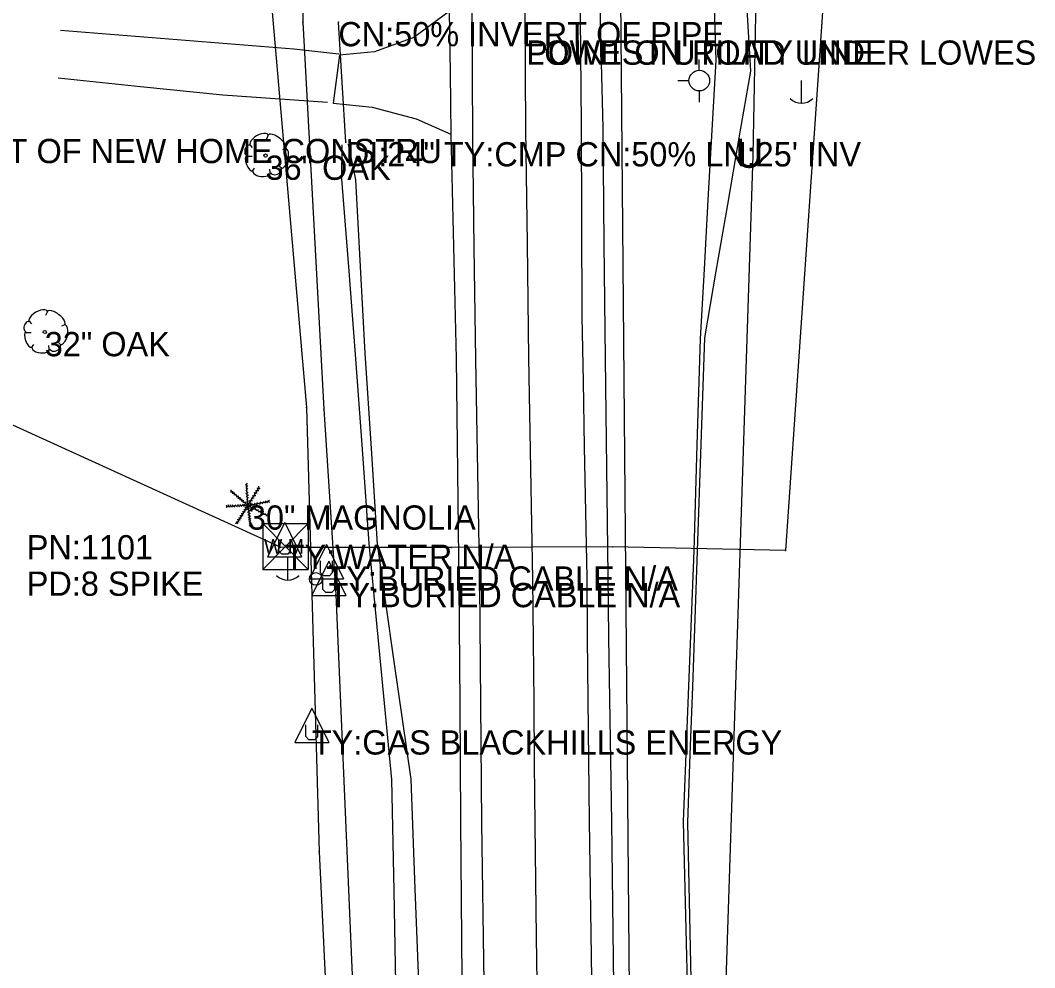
# Model space of a CAD drawing. Extents: x 1804576 to 1805329, y 515859 to 519427.
# Drawn here: x 1804848.7 to 1805057.8, y 517390.7 to 517586 of the extents above; entities that cross this region are included whole.
import ezdxf

# ---------------------------------------------------------------- set-up
doc = ezdxf.new("R2010")
doc.units = 0
for name, color, linetype in [('Default', 7, 'Continuous'), ('S_BASELINE', 7, 'Continuous'), ('S_DITCHLINE', 7, 'Continuous'), ('S_DRG_PT_SYM', 7, 'Continuous'), ('S_DRIVEWAY', 7, 'Continuous'), ('S_EDGE_PAVEMENT', 7, 'Continuous'), ('S_ELECTRIC_UTILITIES_ANNOT', 7, 'Continuous'), ('S_FIBER_OPTIC_CABLE', 7, 'Continuous'), ('S_GAS_UTILITIES', 7, 'Continuous'), ('S_MSC_PT_SYM', 7, 'Continuous'), ('S_PAVEMENT_CROWN', 7, 'Continuous'), ('S_SECONDARY_CTL_ANNOT', 7, 'Continuous'), ('S_SHOULDER', 7, 'Continuous'), ('S_SIDE_DRAIN', 7, 'Continuous'), ('S_SIDE_DRAIN_ANNOT', 7, 'Continuous'), ('S_SURVEY_TEXT_ANNOT', 7, 'Continuous'), ('S_TREE', 7, 'Continuous'), ('S_TREE_ANNOT', 7, 'Continuous'), ('S_UNDERGROUND_CABLE', 7, 'Continuous'), ('S_UTILITY_POLE', 7, 'Continuous'), ('S_UTILITY_POLE_ANNOT', 7, 'Continuous'), ('S_UTL_PT_SYM', 7, 'Continuous'), ('S_WATER_UTILITIES', 7, 'Continuous')]:
    doc.layers.add(name, color=color, linetype=linetype)

msp = doc.modelspace()

# ---------------------------------------------------------------- linework, layer by layer
at = {"layer": 'S_BASELINE'}
msp.add_line((1804979.02, 516850.02), (1804971.48, 517701.71), dxfattribs=at)
at = {"layer": 'S_DITCHLINE'}
for points in [[(1804992.34, 517629.48), (1804990.73, 517622.13), (1804991.4, 517599.91), (1804992.07, 517577.69), (1804991.26, 517563.34), (1804990.45, 517548.98), (1804989.64, 517534.63), (1804988.82, 517520.28), (1804988.18, 517498.42), (1804987.54, 517476.57), (1804986.98, 517462.63), (1804986.42, 517448.7), (1804985.86, 517434.77), (1804985.31, 517420.83), (1804985.82, 517401.34), (1804986.33, 517381.85)], [(1804994.29, 517629.66), (1804996.5, 517622.01), (1804997.84, 517598.75), (1804999.19, 517575.49), (1804996.83, 517561.75), (1804994.47, 517548), (1804992.11, 517534.26), (1804989.75, 517520.52), (1804988.99, 517498.56), (1804988.23, 517476.6), (1804987.73, 517462.59), (1804987.24, 517448.59), (1804986.75, 517434.59), (1804986.25, 517420.59), (1804986.64, 517401.2), (1804987.03, 517381.82)], [(1804915, 517560.29), (1804914.88, 517553.22), (1804916.32, 517535.14), (1804917.76, 517517.05), (1804919.16, 517497.58), (1804920.55, 517478.12), (1804922.88, 517453.78), (1804925.2, 517429.44), (1804925.67, 517406.52), (1804926.14, 517383.6)], [(1804916.31, 517560.43), (1804917.77, 517553.06), (1804918.75, 517535.19), (1804919.74, 517517.32), (1804921, 517497.66), (1804922.27, 517478), (1804925.73, 517453.75), (1804929.18, 517429.5), (1804930.04, 517406.92), (1804930.89, 517384.33)]]:
    msp.add_lwpolyline(points, dxfattribs=at)
at = {"layer": 'S_DRG_PT_SYM'}
for points in [[(1804914.26, 517585.61), (1804914.26, 517585.66), (1804914.26, 517585.61), (1804914.21, 517585.61), (1804914.26, 517585.61), (1804914.26, 517585.56), (1804914.26, 517585.61), (1804914.31, 517585.61)], [(1804915.81, 517560.85), (1804915.81, 517560.9), (1804915.81, 517560.85), (1804915.76, 517560.85), (1804915.81, 517560.85), (1804915.81, 517560.8), (1804915.81, 517560.85), (1804915.86, 517560.85)]]:
    msp.add_lwpolyline(points, dxfattribs=at)
at = {"layer": 'S_DRIVEWAY'}
for points in [[(1804914.38, 517579.01), (1804905.05, 517580.03), (1804881.02, 517581.96), (1804857, 517583.89)], [(1804856.53, 517574.08), (1804873.5, 517572.33), (1804890.47, 517570.59), (1804912, 517569.06)]]:
    msp.add_lwpolyline(points, dxfattribs=at)
at = {"layer": 'S_EDGE_PAVEMENT'}
for points in [[(1804940.46, 517709.42), (1804940.53, 517696.33), (1804940.61, 517683.24), (1804940.74, 517670.08), (1804940.88, 517656.93), (1804941.15, 517639.79), (1804941.42, 517622.66), (1804941.59, 517605.09), (1804941.76, 517587.51), (1804941.82, 517574.8), (1804941.89, 517562.09), (1804942.21, 517539.1), (1804942.54, 517516.11), (1804942.97, 517492.9), (1804943.39, 517469.69), (1804943.57, 517445.12), (1804943.76, 517420.54), (1804944.11, 517396.98), (1804944.47, 517373.41)], [(1804962.48, 517709.57), (1804962.67, 517696.25), (1804962.86, 517682.93), (1804963.02, 517670.14), (1804963.19, 517657.36), (1804963.3, 517639.71), (1804963.4, 517622.06), (1804963.76, 517604.29), (1804964.12, 517586.52), (1804964.31, 517564.57), (1804964.38, 517544.75), (1804964.45, 517524.93), (1804964.7, 517511.48), (1804964.95, 517498.03), (1804965.2, 517484.58), (1804965.45, 517471.12), (1804965.58, 517458.56), (1804965.7, 517445.99), (1804965.83, 517433.42), (1804965.96, 517420.85), (1804966.31, 517397.71), (1804966.66, 517374.58)], [(1804937.12, 517587.77), (1804929.82, 517582.39), (1804921.73, 517579.49), (1804914.51, 517578.77), (1804913.22, 517568.91), (1804921.24, 517568.04), (1804930.31, 517565.67), (1804937.46, 517562.48)]]:
    msp.add_lwpolyline(points, dxfattribs=at)
at = {"layer": 'S_FIBER_OPTIC_CABLE'}
for p, q in [((1805001.76, 517665.3), (1804999.7, 517558.11)), ((1804907.42, 517621.23), (1804906.91, 517585.58)), ((1804906.91, 517585.58), (1804911.25, 517505.78)), ((1804999.7, 517558.11), (1804991.59, 517309.83)), ((1804911.25, 517505.78), (1804913.71, 517467.58)), ((1804913.71, 517467.58), (1804920.05, 517320.35))]:
    msp.add_line(p, q, dxfattribs=at)
at = {"layer": 'S_GAS_UTILITIES'}
for p, q in [((1804900.59, 517587.64), (1804907.72, 517506.16)), ((1804907.72, 517506.16), (1804910.28, 517414.54)), ((1804910.28, 517414.54), (1804914.92, 517321.69))]:
    msp.add_line(p, q, dxfattribs=at)
at = {"layer": 'S_MSC_PT_SYM'}
msp.add_lwpolyline([(1804952.99, 517581.81), (1804952.99, 517581.86), (1804952.99, 517581.81), (1804952.94, 517581.81), (1804952.99, 517581.81), (1804952.99, 517581.76), (1804952.99, 517581.81), (1804953.04, 517581.81)], dxfattribs=at)
at = {"layer": 'S_PAVEMENT_CROWN'}
msp.add_lwpolyline([(1804951.35, 517708.92), (1804951.32, 517696), (1804951.29, 517683.08), (1804951.43, 517670), (1804951.58, 517656.91), (1804951.88, 517639.56), (1804952.18, 517622.21), (1804952.44, 517604.51), (1804952.7, 517586.81), (1804952.87, 517563.54), (1804953.18, 517539.97), (1804953.49, 517516.4), (1804953.89, 517493.53), (1804954.28, 517470.66), (1804954.4, 517458.04), (1804954.53, 517445.43), (1804954.65, 517432.82), (1804954.78, 517420.21), (1804955.07, 517396.93), (1804955.36, 517373.65)], dxfattribs=at)
at = {"layer": 'S_SHOULDER'}
for points in [[(1804939.34, 517709.36), (1804938.44, 517696.01), (1804937.54, 517682.66), (1804937.19, 517670.12), (1804936.83, 517657.58), (1804937.23, 517639.85), (1804937.63, 517622.12), (1804937.37, 517604.95), (1804937.12, 517587.79), (1804937.29, 517575.12), (1804937.45, 517562.46), (1804938.01, 517539.37), (1804938.57, 517516.27), (1804938.84, 517492.83), (1804939.1, 517469.39), (1804939.28, 517445.13), (1804939.46, 517420.88), (1804939.67, 517396.64), (1804939.87, 517372.4)], [(1804963.34, 517709.11), (1804964.59, 517695.88), (1804965.85, 517682.65), (1804966.81, 517670), (1804967.78, 517657.34), (1804967.87, 517639.95), (1804967.96, 517622.56), (1804968.08, 517603.88), (1804968.2, 517585.21), (1804968.75, 517563.81), (1804969, 517539.98), (1804969.26, 517516.16), (1804969.52, 517493.79), (1804969.79, 517471.42), (1804969.98, 517458.76), (1804970.17, 517446.09), (1804970.36, 517433.42), (1804970.55, 517420.76), (1804970.85, 517398.22), (1804971.15, 517375.69)]]:
    msp.add_lwpolyline(points, dxfattribs=at)
at = {"layer": 'S_SIDE_DRAIN'}
msp.add_line((1804915.81, 517560.85), (1804914.26, 517585.61), dxfattribs=at)
at = {"layer": 'S_TREE'}
for p, q in [((1804899.81, 517562.33), (1804899.42, 517561.47)), ((1804896.01, 517560.31), (1804896.52, 517559.73)), ((1804895.36, 517557.99), (1804896.48, 517557.99)), ((1804903.38, 517559.54), (1804902.72, 517559.26)), ((1804896.52, 517554.81), (1804896.98, 517555.51)), ((1804902.6, 517555.43), (1804902.14, 517555.85)), ((1804900.2, 517554.54), (1804900.12, 517555.31)), ((1804854.29, 517525.96), (1804853.9, 517525.1)), ((1804850.49, 517523.94), (1804850.99, 517523.36)), ((1804857.85, 517523.17), (1804857.19, 517522.9)), ((1804849.83, 517521.62), (1804850.96, 517521.62)), ((1804850.99, 517518.44), (1804851.46, 517519.14)), ((1804854.68, 517518.17), (1804854.6, 517518.94)), ((1804857.08, 517519.06), (1804856.61, 517519.49)), ((1804892.33, 517488.71), (1804892.03, 517488.66)), ((1804895.61, 517485.96), (1804892.15, 517488.87)), ((1804892.19, 517488.85), (1804892.19, 517489.15)), ((1804892.5, 517488.6), (1804892.5, 517488.9)), ((1804892.86, 517488.31), (1804892.86, 517488.61)), ((1804895.36, 517490.04), (1804895.13, 517490.24)), ((1804895.39, 517489.48), (1804895.17, 517489.68)), ((1804895.42, 517488.91), (1804895.19, 517489.1)), ((1804895.61, 517485.96), (1804895.34, 517490.4)), ((1804895.35, 517490.29), (1804895.54, 517490.52)), ((1804895.38, 517489.81), (1804895.57, 517490.05)), ((1804895.42, 517489.21), (1804895.6, 517489.45)), ((1804895.45, 517488.5), (1804895.64, 517488.74)), ((1804895.61, 517485.96), (1804897.95, 517489.65)), ((1804897.09, 517488.31), (1804897, 517488.59)), ((1804897.25, 517488.52), (1804897.55, 517488.56)), ((1804897.39, 517488.82), (1804897.3, 517489.11)), ((1804897.57, 517489.01), (1804897.87, 517489.05)), ((1804897.68, 517489.27), (1804897.59, 517489.56)), ((1804897.82, 517489.43), (1804898.12, 517489.48)), ((1804897.93, 517489.61), (1804897.84, 517489.9)), ((1804892.68, 517488.43), (1804892.38, 517488.4)), ((1804893.04, 517488.11), (1804892.74, 517488.08)), ((1804893.5, 517487.73), (1804893.2, 517487.71)), ((1804893.27, 517487.94), (1804893.27, 517488.24)), ((1804893.86, 517487.4), (1804893.56, 517487.38)), ((1804893.68, 517487.61), (1804893.68, 517487.91)), ((1804894.19, 517487.14), (1804893.89, 517487.11)), ((1804894.01, 517487.33), (1804894.01, 517487.63)), ((1804894.53, 517486.84), (1804894.24, 517486.82)), ((1804894.37, 517487.03), (1804894.37, 517487.33)), ((1804894.9, 517486.54), (1804894.6, 517486.52)), ((1804894.74, 517486.72), (1804894.74, 517487.02)), ((1804895.1, 517486.41), (1804895.1, 517486.71)), ((1804895.44, 517488.25), (1804895.22, 517488.45)), ((1804895.48, 517487.65), (1804895.26, 517487.85)), ((1804895.52, 517487.09), (1804895.3, 517487.28)), ((1804895.53, 517486.47), (1804895.31, 517486.67)), ((1804895.52, 517487.94), (1804895.71, 517488.17)), ((1804895.53, 517487.37), (1804895.72, 517487.6)), ((1804895.56, 517486.7), (1804895.75, 517486.93)), ((1804895.61, 517485.96), (1804900.03, 517486.83)), ((1804895.96, 517486.45), (1804896.26, 517486.5)), ((1804896.06, 517486.72), (1804895.97, 517487)), ((1804896.24, 517486.92), (1804896.54, 517486.96)), ((1804896.42, 517487.25), (1804896.33, 517487.53)), ((1804896.58, 517487.46), (1804896.88, 517487.5)), ((1804896.72, 517487.74), (1804896.63, 517488.02)), ((1804896.92, 517486.21), (1804897.12, 517486.43)), ((1804896.93, 517487.98), (1804897.23, 517488.02)), ((1804897.49, 517486.34), (1804897.69, 517486.56)), ((1804897.87, 517486.4), (1804898.12, 517486.24)), ((1804898.12, 517486.48), (1804898.32, 517486.7)), ((1804898.45, 517486.51), (1804898.7, 517486.34)), ((1804898.71, 517486.57), (1804898.91, 517486.79)), ((1804898.96, 517486.62), (1804899.21, 517486.46)), ((1804899.2, 517486.67), (1804899.4, 517486.9)), ((1804899.39, 517486.71), (1804899.64, 517486.55)), ((1804899.64, 517486.76), (1804899.84, 517486.99)), ((1804899.79, 517486.77), (1804900.05, 517486.61)), ((1804899.87, 517486.82), (1804900.07, 517487.04)), ((1804891.24, 517485.75), (1804891.11, 517485.48)), ((1804895.61, 517485.96), (1804891.16, 517485.75)), ((1804891.39, 517485.77), (1804891.22, 517486.02)), ((1804891.59, 517485.78), (1804891.46, 517485.51)), ((1804891.78, 517485.8), (1804891.61, 517486.05)), ((1804891.93, 517485.8), (1804891.8, 517485.53)), ((1804892.18, 517485.8), (1804892.01, 517486.05)), ((1804892.35, 517485.81), (1804892.22, 517485.54)), ((1804892.58, 517485.83), (1804892.41, 517486.07)), ((1804892.86, 517485.83), (1804892.73, 517485.57)), ((1804893.15, 517485.84), (1804892.98, 517486.09)), ((1804895.61, 517485.96), (1804893.23, 517482.19)), ((1804893.43, 517485.86), (1804893.29, 517485.59)), ((1804893.7, 517485.88), (1804893.53, 517486.13)), ((1804893.91, 517485.88), (1804893.77, 517485.61)), ((1804894.18, 517485.89), (1804894.01, 517486.14)), ((1804894.38, 517485.91), (1804894.25, 517485.64)), ((1804894.62, 517485.93), (1804894.45, 517486.18)), ((1804894.77, 517484.65), (1804894.47, 517484.62)), ((1804894.66, 517484.45), (1804894.73, 517484.16)), ((1804894.84, 517485.91), (1804894.7, 517485.64)), ((1804895.04, 517485.1), (1804894.75, 517485.06)), ((1804894.95, 517485.97), (1804894.79, 517486.22)), ((1804894.92, 517484.87), (1804894.99, 517484.58)), ((1804895.26, 517486.25), (1804894.96, 517486.22)), ((1804895.28, 517485.47), (1804894.99, 517485.43)), ((1804895.23, 517485.92), (1804895.09, 517485.66)), ((1804895.19, 517485.31), (1804895.27, 517485.01)), ((1804895.41, 517485.64), (1804895.48, 517485.35)), ((1804895.67, 517485.29), (1804895.48, 517485.06)), ((1804895.74, 517484.71), (1804895.54, 517484.48)), ((1804895.61, 517485.96), (1804899.53, 517483.92)), ((1804895.61, 517485.96), (1804896.14, 517481.59)), ((1804895.69, 517485.54), (1804895.95, 517485.38)), ((1804895.73, 517484.98), (1804895.98, 517484.83)), ((1804895.81, 517484.41), (1804896.07, 517484.26)), ((1804895.94, 517485.78), (1804896.21, 517485.92)), ((1804895.99, 517486.05), (1804896.19, 517486.27)), ((1804896.12, 517485.69), (1804896.19, 517485.39)), ((1804896.23, 517486.08), (1804896.49, 517485.92)), ((1804896.39, 517486.11), (1804896.59, 517486.33)), ((1804896.42, 517485.56), (1804896.68, 517485.7)), ((1804896.7, 517485.38), (1804896.77, 517485.09)), ((1804896.75, 517486.16), (1804897, 517486)), ((1804896.97, 517485.25), (1804897.24, 517485.39)), ((1804897.24, 517485.11), (1804897.31, 517484.81)), ((1804897.26, 517486.27), (1804897.52, 517486.11)), ((1804897.53, 517484.97), (1804897.79, 517485.11)), ((1804897.76, 517484.83), (1804897.83, 517484.54)), ((1804898.01, 517484.71), (1804898.28, 517484.85)), ((1804898.3, 517484.54), (1804898.37, 517484.25)), ((1804898.55, 517484.44), (1804898.81, 517484.58)), ((1804899.1, 517484.16), (1804899.36, 517484.3)), ((1804893.26, 517482.27), (1804892.97, 517482.24)), ((1804893.46, 517482.58), (1804893.17, 517482.54)), ((1804893.39, 517482.43), (1804893.46, 517482.14)), ((1804893.72, 517482.99), (1804893.42, 517482.96)), ((1804893.61, 517482.78), (1804893.69, 517482.49)), ((1804893.95, 517483.36), (1804893.66, 517483.33)), ((1804893.87, 517483.18), (1804893.95, 517482.89)), ((1804894.25, 517483.81), (1804893.95, 517483.78)), ((1804894.12, 517483.56), (1804894.19, 517483.27)), ((1804894.52, 517484.23), (1804894.22, 517484.2)), ((1804894.4, 517484.03), (1804894.48, 517483.74)), ((1804895.82, 517484.15), (1804895.63, 517483.92)), ((1804895.89, 517483.58), (1804895.7, 517483.35)), ((1804895.96, 517483.12), (1804895.76, 517482.89)), ((1804896, 517482.74), (1804895.8, 517482.51)), ((1804896.05, 517482.29), (1804895.86, 517482.07)), ((1804895.88, 517483.87), (1804896.13, 517483.71)), ((1804895.95, 517483.36), (1804896.2, 517483.2)), ((1804895.98, 517482.92), (1804896.24, 517482.77)), ((1804896.03, 517482.52), (1804896.28, 517482.36)), ((1804898.81, 517484.28), (1804898.88, 517483.99)), ((1804899.3, 517484.03), (1804899.37, 517483.74)), ((1804899.49, 517483.96), (1804899.76, 517484.1)), ((1804896.1, 517481.87), (1804895.9, 517481.65)), ((1804896.09, 517482.05), (1804896.35, 517481.9)), ((1804896.13, 517481.71), (1804896.38, 517481.56))]:
    msp.add_line(p, q, dxfattribs=at)
for centre in [(1804899.25, 517558.08), (1804853.73, 517521.71)]:
    msp.add_circle(centre, 0.341, dxfattribs=at)
for centre, major_axis, ratio, start_param, end_param in [((1804897.92, 517561.28), (1.86, 1.08), 0.471018, 0, 3.141593), ((1804901.57, 517560.96), (-1.81, 1.36), 0.405113, 3.141593, 6.283186), ((1804895.68, 517559.17), (0.31, 1.03), 0.646762, 0, 3.141593), ((1804902.93, 517557.55), (0.46, 2.04), 0.482994, 3.141593, 6.283185), ((1804895.99, 517556.52), (-0.61, 1.6), 0.420543, 6.283185, 9.424777), ((1804901.41, 517555.03), (1.09, 0.46), 0.711534, 3.141592, 6.283185), ((1804898.45, 517554.74), (-1.83, 0.19), 0.529943, 0, 3.141593), ((1804852.39, 517524.91), (1.86, 1.08), 0.471018, 0, 3.141593), ((1804856.05, 517524.59), (-1.81, 1.36), 0.405113, 3.141593, 6.283186), ((1804850.16, 517522.8), (0.31, 1.03), 0.646762, 0, 3.141593), ((1804857.4, 517521.18), (0.46, 2.04), 0.482994, 3.141593, 6.283185), ((1804850.46, 517520.15), (-0.61, 1.6), 0.420543, 6.283185, 9.424777), ((1804852.93, 517518.37), (-1.83, 0.19), 0.529943, 0, 3.141593), ((1804855.88, 517518.66), (1.09, 0.46), 0.711534, 3.141592, 6.283185)]:
    msp.add_ellipse(centre, major_axis=major_axis, ratio=ratio, start_param=start_param, end_param=end_param, dxfattribs=at)
at = {"layer": 'S_UNDERGROUND_CABLE'}
for p, q in [((1804903.2, 517482.42), (1804899.67, 517475.33)), ((1804903.2, 517482.42), (1804906.68, 517475.33)), ((1804902, 517476.57), (1804902, 517479.01)), ((1804904.36, 517479.01), (1804904.36, 517476.57)), ((1804902.62, 517475.91), (1804902, 517476.57)), ((1804904.36, 517476.57), (1804903.82, 517475.91)), ((1804911.8, 517477.92), (1804908.28, 517470.83)), ((1804911.8, 517477.92), (1804915.29, 517470.83)), ((1804899.67, 517475.33), (1804906.68, 517475.33)), ((1804903.82, 517475.91), (1804902.62, 517475.91)), ((1804912.28, 517474.5), (1804908.76, 517467.41)), ((1804910.6, 517472.07), (1804910.6, 517474.51)), ((1804912.28, 517474.5), (1804915.77, 517467.41)), ((1804912.96, 517474.51), (1804912.96, 517472.07)), ((1804911.22, 517471.41), (1804910.6, 517472.07)), ((1804912.96, 517472.07), (1804912.42, 517471.41)), ((1804908.28, 517470.83), (1804915.29, 517470.83)), ((1804911.08, 517468.65), (1804911.08, 517471.09)), ((1804912.42, 517471.41), (1804911.22, 517471.41)), ((1804913.44, 517471.09), (1804913.44, 517468.65)), ((1804911.7, 517467.99), (1804911.08, 517468.65)), ((1804912.9, 517467.99), (1804911.7, 517467.99)), ((1804913.44, 517468.65), (1804912.9, 517467.99)), ((1804908.76, 517467.41), (1804915.77, 517467.41)), ((1804908.79, 517444.14), (1804905.26, 517437.05)), ((1804908.79, 517444.14), (1804912.27, 517437.05)), ((1804907.58, 517438.29), (1804907.58, 517440.73)), ((1804909.95, 517440.73), (1804909.95, 517438.29)), ((1804908.2, 517437.63), (1804907.58, 517438.29)), ((1804909.95, 517438.29), (1804909.41, 517437.63)), ((1804905.26, 517437.05), (1804912.27, 517437.05)), ((1804909.41, 517437.63), (1804908.2, 517437.63))]:
    msp.add_line(p, q, dxfattribs=at)
at = {"layer": 'S_UTILITY_POLE'}
for p, q in [((1804988.67, 517575.64), (1804988.67, 517577.89)), ((1804986.57, 517573.51), (1804984.25, 517573.51)), ((1805009.67, 517573.59), (1805009.67, 517568.87)), ((1804988.74, 517569.1), (1804988.74, 517571.42)), ((1804903.78, 517475.29), (1804903.78, 517470.56))]:
    msp.add_line(p, q, dxfattribs=at)
for centre, radius in [((1804988.67, 517573.53), 2.13), ((1804909.62, 517470.8), 1.31)]:
    msp.add_circle(centre, radius, dxfattribs=at)
for centre in [(1805009.73, 517572.29), (1804903.84, 517473.99)]:
    msp.add_arc(centre, 3.41, 226.3972, 313.6028, dxfattribs=at)
at = {"layer": 'S_UTL_PT_SYM'}
for points in [[(1804906.91, 517585.58), (1804906.91, 517585.63), (1804906.91, 517585.58), (1804906.86, 517585.58), (1804906.91, 517585.58), (1804906.91, 517585.53), (1804906.91, 517585.58), (1804906.96, 517585.58)], [(1804952.99, 517581.81), (1804952.99, 517581.86), (1804952.99, 517581.81), (1804952.94, 517581.81), (1804952.99, 517581.81), (1804952.99, 517581.76), (1804952.99, 517581.81), (1804953.04, 517581.81)], [(1804907.72, 517506.16), (1804907.72, 517506.21), (1804907.72, 517506.16), (1804907.67, 517506.16), (1804907.72, 517506.16), (1804907.72, 517506.11), (1804907.72, 517506.16), (1804907.77, 517506.16)], [(1804911.25, 517505.78), (1804911.25, 517505.83), (1804911.25, 517505.78), (1804911.2, 517505.78), (1804911.25, 517505.78), (1804911.25, 517505.73), (1804911.25, 517505.78), (1804911.3, 517505.78)], [(1804902.33, 517477.35), (1804902.33, 517477.4), (1804902.33, 517477.35), (1804902.28, 517477.35), (1804902.33, 517477.35), (1804902.33, 517477.3), (1804902.33, 517477.35), (1804902.38, 517477.35)], [(1804904.73, 517477.29), (1804904.73, 517477.34), (1804904.73, 517477.29), (1804904.68, 517477.29), (1804904.73, 517477.29), (1804904.73, 517477.24), (1804904.73, 517477.29), (1804904.78, 517477.29)], [(1804937.53, 517477.26), (1804937.53, 517477.31), (1804937.53, 517477.26), (1804937.48, 517477.26), (1804937.53, 517477.26), (1804937.53, 517477.21), (1804937.53, 517477.26), (1804937.58, 517477.26)], [(1804970.8, 517477.42), (1804970.8, 517477.47), (1804970.8, 517477.42), (1804970.75, 517477.42), (1804970.8, 517477.42), (1804970.8, 517477.37), (1804970.8, 517477.42), (1804970.85, 517477.42)], [(1805006.45, 517476.66), (1805006.45, 517476.71), (1805006.45, 517476.66), (1805006.4, 517476.66), (1805006.45, 517476.66), (1805006.45, 517476.61), (1805006.45, 517476.66), (1805006.5, 517476.66)], [(1804913.71, 517467.58), (1804913.71, 517467.63), (1804913.71, 517467.58), (1804913.66, 517467.58), (1804913.71, 517467.58), (1804913.71, 517467.53), (1804913.71, 517467.58), (1804913.76, 517467.58)], [(1804910.28, 517414.54), (1804910.28, 517414.59), (1804910.28, 517414.54), (1804910.23, 517414.54), (1804910.28, 517414.54), (1804910.28, 517414.49), (1804910.28, 517414.54), (1804910.33, 517414.54)]]:
    msp.add_lwpolyline(points, dxfattribs=at)
at = {"layer": 'S_WATER_UTILITIES'}
for p, q in [((1805017.05, 517631.36), (1805006.45, 517476.66)), ((1804902.33, 517477.35), (1804841.05, 517505.28)), ((1804898.71, 517482.24), (1804908.05, 517482.24)), ((1804898.71, 517482.24), (1804898.71, 517472.75)), ((1804898.71, 517482.24), (1804908.05, 517472.75)), ((1804908.05, 517482.24), (1804898.71, 517472.75)), ((1804908.05, 517482.24), (1804908.05, 517472.75)), ((1804904.73, 517477.29), (1804902.33, 517477.35)), ((1804937.53, 517477.26), (1804904.73, 517477.29)), ((1804970.8, 517477.42), (1804937.53, 517477.26)), ((1805006.45, 517476.66), (1804970.8, 517477.42)), ((1804898.71, 517472.75), (1804908.05, 517472.75))]:
    msp.add_line(p, q, dxfattribs=at)

# ---------------------------------------------------------------- texts
at = {"layer": 'Default'}
msp.add_text('U', height=6, dxfattribs=at).set_placement((1804996.07, 517555.56))
at = {"layer": 'S_ELECTRIC_UTILITIES_ANNOT'}
msp.add_text('LOWEST UTILITY LINE', height=5, dxfattribs=at).set_placement((1804952.99, 517576.81))
at = {"layer": 'S_SECONDARY_CTL_ANNOT'}
for s, p in [('PN:1101', (1804850.03, 517474.83)), ('PD:8 SPIKE', (1804850.03, 517467.33))]:
    msp.add_text(s, height=5, dxfattribs=at).set_placement(p)
at = {"layer": 'S_SIDE_DRAIN_ANNOT'}
for s, p in [('CN:50% INVERT OF PIPE', (1804914.26, 517580.61)), ('DI:24" TY:CMP CN:50% LN:25\' INV', (1804915.81, 517555.85))]:
    msp.add_text(s, height=5, dxfattribs=at).set_placement(p)
at = {"layer": 'S_SURVEY_TEXT_ANNOT'}
for s, p in [('POINT ON ROAD UNDER LOWES', (1804952.99, 517576.81)), ('FRONT OF NEW HOME CONSTRU', (1804827.16, 517556.52))]:
    msp.add_text(s, height=5, dxfattribs=at).set_placement(p)
at = {"layer": 'S_TREE_ANNOT'}
for s, p in [('36" OAK', (1804899.25, 517553.08)), ('32" OAK', (1804853.73, 517516.71)), ('30" MAGNOLIA', (1804895.61, 517480.96))]:
    msp.add_text(s, height=5, dxfattribs=at).set_placement(p)
at = {"layer": 'S_UTILITY_POLE_ANNOT'}
for s, p in [('TY:WATER N/A', (1804903.2, 517472.88)), ('TY:BURIED CABLE N/A', (1804911.8, 517468.39)), ('TY:BURIED CABLE N/A', (1804912.28, 517464.97)), ('TY:GAS BLACKHILLS ENERGY', (1804908.79, 517434.6))]:
    msp.add_text(s, height=5, dxfattribs=at).set_placement(p)
at = {"layer": 'S_WATER_UTILITIES'}
msp.add_text('W M', height=3, dxfattribs=at).set_placement((1804898.92, 517476.01))

doc.saveas('drawing.dxf')
